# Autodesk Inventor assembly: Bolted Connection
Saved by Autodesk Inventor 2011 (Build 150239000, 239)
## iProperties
Created: 2020-12
Part Number: Bolted Connection
Document SubType Name: Assembly
Designer: PC
ClientObjectVersion: 1
Author: PC
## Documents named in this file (3)
- C:\Users\PC\Documents\Inventor\workshop-crane-powered-by-drill\telescopic-tube\Design Accelerator\Bolted Connection1.iam
- C:\Users\PC\Documents\Inventor\Content Center Files\R2011\en-US\DIN 931-1\DIN 931-1 - M14 x 80.ipt
- C:\Users\PC\Documents\Inventor\Content Center Files\R2011\en-US\DIN 555\DIN 555-5 - M14.ipt
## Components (2 placed, 2 different names)
1. DIN 931-1 - replaced by DIN EN 24014 M14 x 80:1
2. DIN 555 - replaced by DIN EN 24034 M14:1
